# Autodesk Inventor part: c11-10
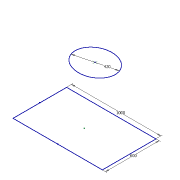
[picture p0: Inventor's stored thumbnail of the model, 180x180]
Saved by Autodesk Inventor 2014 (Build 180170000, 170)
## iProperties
Created: 2011-01
Part Number: c11-10
Material: Aluminum 6061
Document SubType Name: Sheet Metal
Designer: Thom Tremblay
Density: 2.71 g/cm^3
Sheet Metal Rule: Aluminum 3 mm
Appearance: Glossy - Gold
Author: Thom Tremblay
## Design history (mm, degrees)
sketch "Sketch1"
  geometry: L1 (-500, -300)-(500, -300); L2 (500, -300)-(500, 300); L3 (500, 300)-(-500, 300); L4 (-500, 300)-(-500, -300); 3 further points
  constraints: 8 end point, 2 midpoint, 2 parallel, 1 horizontal, 1 horizontal alignment, 1 perpendicular, 1 vertical alignment
  dimensions: "d0" = 1000 distance of L3.end L2.end; "d1" = 600 distance of L2.end L1.end
sketch "Sketch2"
  geometry: C1 r 210 at (0, 0); 1 further point
  constraints: 1 centre point, 1 coincident
  dimensions: "d10" = 420 diameter of C1
other parameters: "Thickness" = 3 (derived), "BendRadius" = 2 (derived), "BendReliefWidth" = 3 (= Thickness), "BendReliefDepth" = 1.5 (= 0.5 x Thickness), "CornerReliefSize" = 12 (= 4 x Thickness), "SeamGap" = 0.01, "MinimumRemnant" = 6 (= 2 x Thickness), "TransitionRadius" = 2 (= BendRadius), "JacobiRadiusSize" = 2 (= BendRadius), "GapSize" = 1.5 (= 0.5 x Thickness), "d7" = 5 deg, "d8" = -5 deg, "d9" = 0
